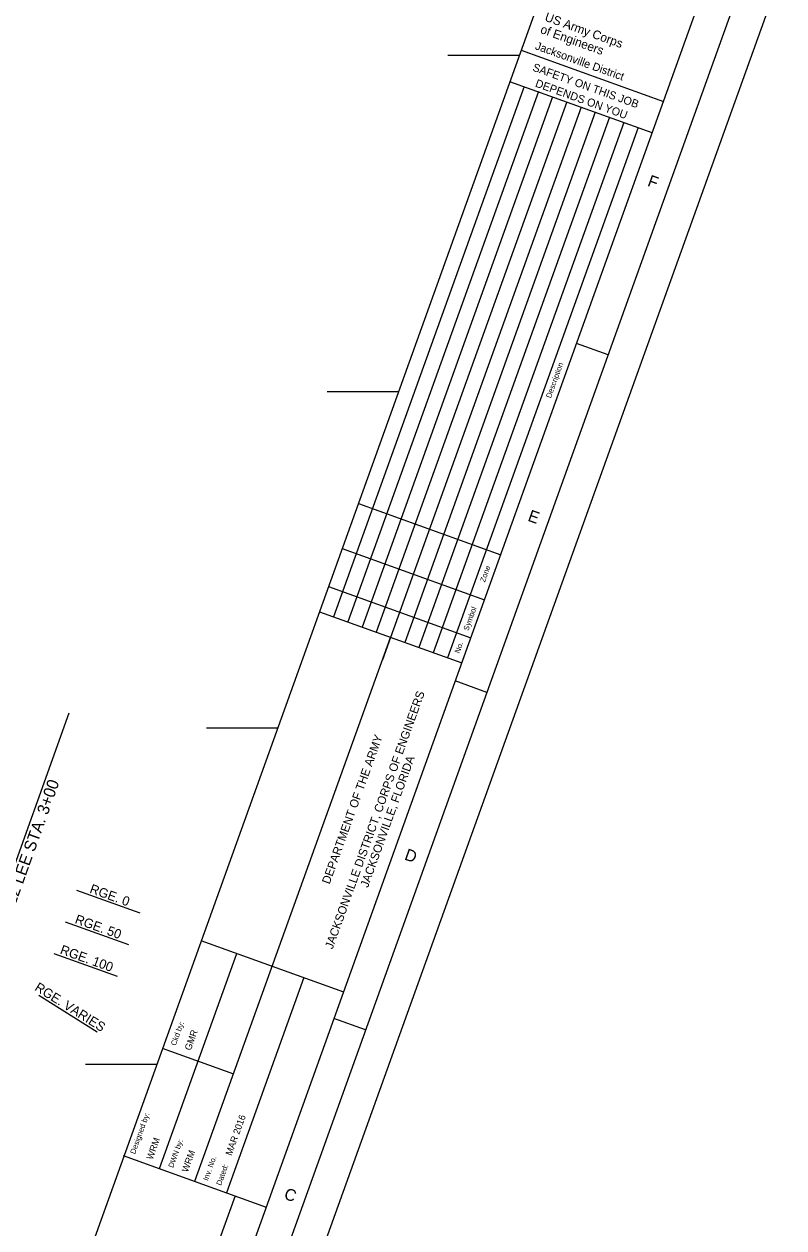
# Model space of a CAD drawing. Extents: x 612209 to 617500, y 780934 to 785622.
# Drawn here: x 616370 to 617500, y 782256 to 784046 of the extents above; entities that cross this region are included whole.
import ezdxf

# ---------------------------------------------------------------- set-up
doc = ezdxf.new("R2010")
doc.units = 0
for name, color, linetype in [('G-ANNO-NPLT', 7, 'Continuous'), ('G-ANNO-TEXT-DRWG', 7, 'Continuous'), ('G-ANNO-TEXT-PROJ', 7, 'Continuous'), ('G-ANNO-TEXT-TTLB', 7, 'Continuous'), ('G-ANNO-TTLB', 7, 'Continuous'), ('V-ALGN-TEXT', 7, 'Continuous'), ('V-ANNO-MATC', 7, 'Continuous'), ('V-ANNO-MATC-IDEN', 7, 'Continuous'), ('V-TOPO-COOR-STAT', 7, 'Continuous')]:
    doc.layers.add(name, color=color, linetype=linetype)

msp = doc.modelspace()

# ---------------------------------------------------------------- linework, layer by layer
at = {"layer": 'G-ANNO-NPLT'}
msp.add_lwpolyline([(613359.5, 785622.2), (617500, 784133.6), (616349.7, 780934.1), (612209.2, 782422.8)], close=True, dxfattribs=at)
at = {"layer": 'G-ANNO-TTLB'}
for p, q in [((617160.3, 784149.5), (616077.7, 781138.2)), ((617109.2, 784007.2), (617320.9, 783931)), ((617092, 783961.1), (617303.7, 783885)), ((617113.6, 783953.4), (616830.1, 783164.9)), ((617134.8, 783945.8), (616851.3, 783157.3)), ((617155.9, 783938.2), (616872.4, 783149.7)), ((617177.1, 783930.5), (616893.6, 783142)), ((617198.3, 783922.9), (616914.8, 783134.4)), ((617219.4, 783915.3), (616936, 783126.8)), ((617240.6, 783907.7), (616957.1, 783119.2)), ((617261.8, 783900.1), (616978.3, 783111.6)), ((617283, 783892.5), (616999.5, 783104)), ((617238.7, 783554.4), (617191.6, 783571.3)), ((616867, 783333.4), (617078.7, 783257.3)), ((616842.9, 783266.4), (617054.6, 783190.3)), ((616822.6, 783209.9), (617034.3, 783133.8)), ((616809.1, 783172.4), (617020.8, 783096.3)), ((616623.5, 782325.7), (616915, 783134.4)), ((616915, 783134.4), (616903, 783101.1)), ((617058.2, 783052.5), (617011.2, 783069.5)), ((616632.5, 782683.5), (616844.9, 782607.1)), ((616570.9, 782344.7), (616686, 782664.2)), ((616785.7, 782628.4), (616670.8, 782308.7)), ((616877.8, 782550.7), (616830.7, 782567.6)), ((616575, 782523.6), (616681.1, 782485.5)), ((616517.1, 782364), (616730, 782287.4)), ((616683.6, 782304.1), (616564.7, 781973.4))]:
    msp.add_line(p, q, dxfattribs=at)
for points in [[(612273.2, 782452.9), (616319.6, 780998.1), (617436.1, 784103.5), (613389.7, 785558.3)], [(617372.1, 784073.3), (613490.4, 785468.9), (612407.7, 782457.7), (616289.5, 781062.1)]]:
    msp.add_lwpolyline(points, close=True, dxfattribs=at)
at = {"layer": 'V-ALGN-TEXT'}
for p, q in [((616447.8, 782758.5), (616541.9, 782724.7)), ((616430.9, 782711.5), (616525, 782677.7)), ((616414, 782664.4), (616508.1, 782630.6)), ((616391.7, 782602.6), (616478.4, 782548.1))]:
    msp.add_line(p, q, dxfattribs=at)
at = {"layer": 'V-ANNO-MATC'}
msp.add_line((616436.2, 783021.8), (616237.1, 782468.2), dxfattribs=at)
at = {"layer": 'V-TOPO-COOR-STAT'}
for p, q in [((617000.3, 784000), (617106.6, 784000)), ((616820.6, 783500), (616926.8, 783500)), ((616640.8, 783000), (616747.1, 783000)), ((616461, 782500), (616567.3, 782500))]:
    msp.add_line(p, q, dxfattribs=at)

# ---------------------------------------------------------------- texts
at = {"layer": 'G-ANNO-TEXT-DRWG'}
for s, p in [('GMR', (616617.6, 782519.3)), ('WRM', (616560.8, 782356.9)), ('WRM', (616613.2, 782338.3))]:
    msp.add_text(s, height=10, rotation=70.2251, dxfattribs=at).set_placement(p)
at = {"layer": 'G-ANNO-TEXT-PROJ'}
msp.add_text('MAR 2016', height=10, rotation=70.2251, dxfattribs=at).set_placement((616678.3, 782363))
at = {"layer": 'G-ANNO-TEXT-TTLB'}
for s, height, rotation, p in [('US Army Corps', 13.086, 340.2251, (617143.2, 784051.5)), ('of Engineers', 13.086, 340.2251, (617136.6, 784033.3)), ('Jacksonville District', 11.9, 340.2251, (617129, 784009.1)), ('SAFETY ON THIS JOB', 11.9, 340.2251, (617125.1, 783977.2)), ('DEPENDS ON YOU', 11.9, 340.2251, (617129.1, 783953.5)), ('Description', 8, 70.2251, (617153.3, 783489.4)), ('Zone', 8, 70.2251, (617055.2, 783215.8)), ('Symbol', 8, 70.2251, (617030.5, 783143.5)), ('No.', 8, 70.2251, (617017.3, 783109.9)), ('JACKSONVILLE DISTRICT, CORPS OF ENGINEERS', 12.5, 70.2251, (616828.6, 782670)), ('DEPARTMENT OF THE ARMY', 12.5, 70.2251, (616824.1, 782766.6)), ('JACKSONVILLE, FLORIDA', 12.5, 70.2251, (616881.2, 782761.5)), ('Ckd by:', 8, 70.2251, (616595.2, 782526.5)), ('Designed by:', 8, 70.2251, (616534.7, 782365.4)), ('DWN by:', 8, 70.2251, (616591.4, 782345)), ('Inv. No.', 8, 70.2251, (616643.1, 782325.7)), ('Dated:', 8, 70.2251, (616662.7, 782318.7))]:
    msp.add_text(s, height=height, rotation=rotation, dxfattribs=at).set_placement(p)
at = {"layer": 'G-ANNO-TTLB'}
for s, p in [('F', (617295.9, 783806)), ('E', (617117.8, 783308.1)), ('D', (616934.3, 782804.4)), ('C', (616755, 782300.1))]:
    msp.add_text(s, height=17.5, rotation=340.2251, dxfattribs=at).set_placement(p)
at = {"layer": 'V-ALGN-TEXT'}
for s, rotation, p in [('RGE. 0', 340.2251, (616466.2, 782754.9)), ('RGE. 50', 340.2251, (616444.2, 782709.7)), ('RGE. 100', 340.2251, (616422.2, 782664.4)), ('RGE. VARIES', 327.8644, (616384.3, 782610.5))]:
    msp.add_text(s, height=13.92, rotation=rotation, dxfattribs=at).set_placement(p)
at = {"layer": 'V-ANNO-MATC-IDEN'}
msp.add_text('MATCHLINE SHEET NO. 012 LEE STA. 3+00', height=17.52, rotation=70.2251, dxfattribs=at).set_placement((616259.3, 782465.1))

doc.saveas('drawing.dxf')
